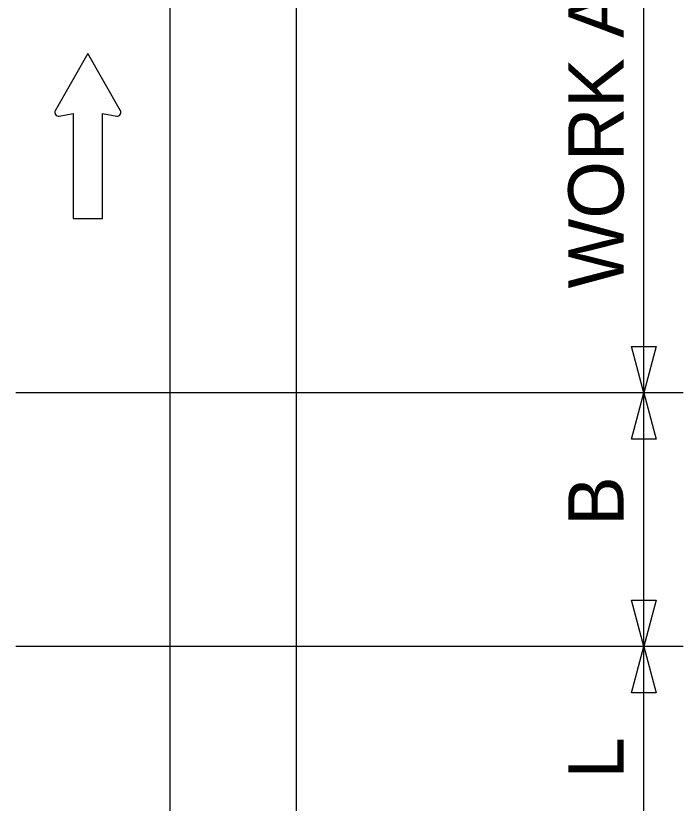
# Model space of a CAD drawing. Extents: x 16731 to 18475, y 7003 to 8262.
# Drawn here: x 17093.7 to 17178.2, y 7787.1 to 7886.8 of the extents above; entities that cross this region are included whole.
import ezdxf

# ---------------------------------------------------------------- set-up
doc = ezdxf.new("R2010")
doc.units = 0
for name, color, linetype in [('MT_SCRATCH_LEVEL_E', 7, 'Continuous'), ('PAVT_EDGE_EX', 7, 'Continuous'), ('TYPICAL_TEXT_DIMEN_PR', 7, 'Continuous')]:
    doc.layers.add(name, color=color, linetype=linetype)

msp = doc.modelspace()

# ---------------------------------------------------------------- linework, layer by layer
at = {"layer": 'MT_SCRATCH_LEVEL_E'}
for p, q in [((17102.855, 7881.982), (17098.744, 7874.742)), ((17102.855, 7881.982), (17098.744, 7874.742)), ((17107.001, 7874.742), (17102.855, 7881.982)), ((17107.001, 7874.742), (17102.855, 7881.982)), ((17099.225, 7874.058), (17101.003, 7874.373)), ((17099.225, 7874.058), (17101.003, 7874.373)), ((17101.003, 7874.373), (17101.003, 7861.116)), ((17101.003, 7874.373), (17101.003, 7861.116)), ((17104.745, 7861.116), (17104.745, 7874.373)), ((17104.745, 7874.373), (17106.522, 7874.058)), ((17104.745, 7861.116), (17104.745, 7874.373)), ((17104.745, 7874.373), (17106.522, 7874.058)), ((17101.003, 7861.116), (17104.745, 7861.116)), ((17101.003, 7861.116), (17104.745, 7861.116))]:
    msp.add_line(p, q, dxfattribs=at)
for centre, start, end in [((17106.592, 7874.518), 260.03619, 29.77312), ((17106.592, 7874.518), 260.03619, 29.77312), ((17099.151, 7874.517), 150.42484, 279.96381), ((17099.151, 7874.517), 150.42484, 279.96381)]:
    msp.add_arc(centre, 0.463, start, end, dxfattribs=at)
at = {"layer": 'PAVT_EDGE_EX'}
for p, q in [((17113.238, 8211.758), (17113.238, 7353.85)), ((17129.238, 8211.758), (17129.238, 7353.85))]:
    msp.add_line(p, q, dxfattribs=at)
at = {"layer": 'TYPICAL_TEXT_DIMEN_PR'}
for p, q in [((17173.238, 7839.028), (17173.238, 7952.753)), ((17173.238, 7839.028), (17171.668, 7844.89)), ((17171.668, 7844.89), (17173.238, 7844.89)), ((17173.238, 7844.89), (17174.808, 7844.89)), ((17174.808, 7844.89), (17173.238, 7839.028)), ((17178.238, 7839.028), (17093.742, 7839.028)), ((17171.668, 7833.166), (17173.238, 7839.028)), ((17173.238, 7806.969), (17173.238, 7839.028)), ((17173.238, 7839.028), (17174.808, 7833.166)), ((17173.238, 7833.166), (17171.668, 7833.166)), ((17174.808, 7833.166), (17173.238, 7833.166)), ((17173.238, 7806.969), (17171.668, 7812.831)), ((17171.668, 7812.831), (17173.238, 7812.831)), ((17173.238, 7812.831), (17174.808, 7812.831)), ((17174.808, 7812.831), (17173.238, 7806.969)), ((17178.238, 7806.969), (17093.742, 7806.969)), ((17171.668, 7801.107), (17173.238, 7806.969)), ((17173.238, 7806.969), (17174.808, 7801.107)), ((17173.238, 7776.394), (17173.238, 7806.969)), ((17173.238, 7801.107), (17171.668, 7801.107)), ((17174.808, 7801.107), (17173.238, 7801.107))]:
    msp.add_line(p, q, dxfattribs=at)

# ---------------------------------------------------------------- texts
for s, p in [('WORK AREA VARIES', (17170.679, 7852.248)), ('B', (17170.679, 7822.233)), ('L', (17170.679, 7790.262))]:
    msp.add_text(s, height=7, rotation=90, dxfattribs=at).set_placement(p)

doc.saveas('drawing.dxf')
